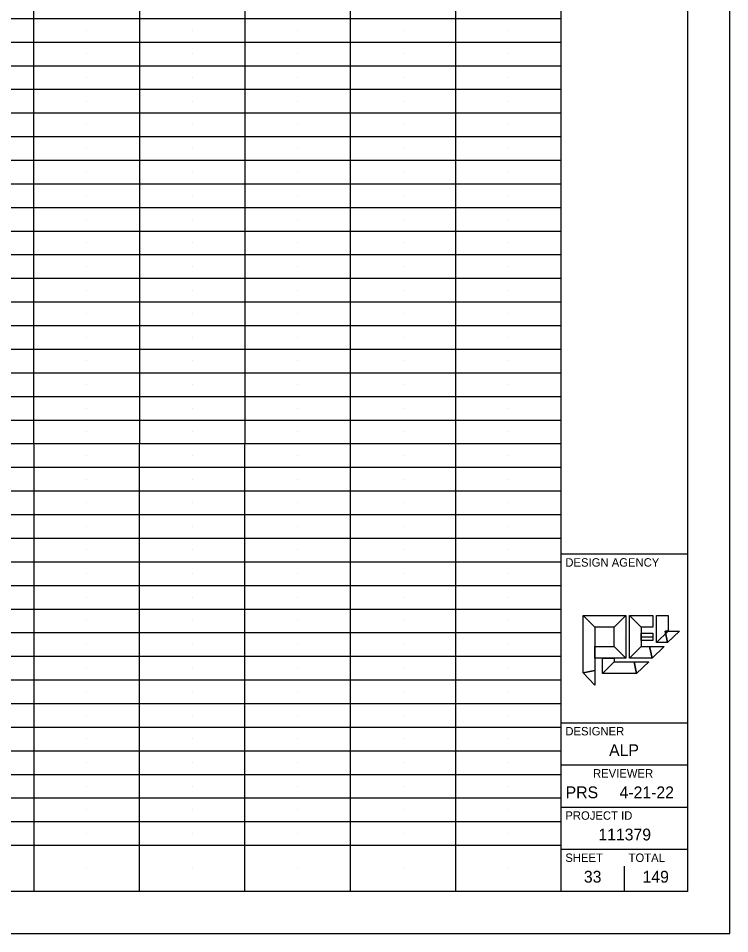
# Model space of a CAD drawing. Extents: x 2073163.9 to 2073197.9, y 634076.5 to 634098.5.
# Drawn here: x 2073189.51 to 2073197.95, y 634076.55 to 634087.4 of the extents above; entities that cross this region are included whole.
import ezdxf

# ---------------------------------------------------------------- set-up
doc = ezdxf.new("R2010")
doc.units = 0
for name, color, linetype in [('Default', 7, 'Continuous'), ('SH_Border', 7, 'Continuous'), ('SH_Cut_Line', 7, 'Continuous'), ('SH_Data', 7, 'Continuous')]:
    doc.layers.add(name, color=color, linetype=linetype)

msp = doc.modelspace()

# ---------------------------------------------------------------- linework, layer by layer
at = {"layer": 'Default'}
msp.add_line((2073196.896, 634080.068), (2073197.032, 634080.068), dxfattribs=at)
for points in [[(2073196.209, 634079.643), (2073196.209, 634080.32), (2073196.347, 634080.183), (2073196.347, 634079.671)], [(2073196.209, 634080.32), (2073196.712, 634080.32), (2073196.576, 634080.183), (2073196.347, 634080.183)], [(2073196.712, 634080.32), (2073196.712, 634079.817), (2073196.576, 634079.954), (2073196.576, 634080.183)], [(2073196.758, 634079.817), (2073196.758, 634080.32), (2073196.896, 634080.183), (2073196.896, 634079.954)], [(2073196.758, 634080.32), (2073197.032, 634080.32), (2073197.032, 634080.183), (2073196.896, 634080.183)], [(2073197.078, 634080), (2073197.078, 634080.32), (2073197.216, 634080.32), (2073197.216, 634080.137)], [(2073197.032, 634080.11), (2073197.032, 634080.026), (2073196.897, 634080.026), (2073196.897, 634080.11)], [(2073197.207, 634080), (2073197.078, 634080), (2073197.216, 634080.137), (2073197.179, 634080.137)], [(2073197.352, 634080.137), (2073197.207, 634080), (2073197.179, 634080.137)], [(2073196.712, 634079.817), (2073196.347, 634079.817), (2073196.347, 634079.954), (2073196.576, 634079.954)], [(2073197.024, 634079.817), (2073196.758, 634079.817), (2073196.896, 634079.954), (2073196.996, 634079.954)], [(2073197.169, 634079.954), (2073197.024, 634079.817), (2073196.996, 634079.954)], [(2073196.438, 634079.634), (2073196.438, 634079.817), (2073196.576, 634079.817), (2073196.576, 634079.771)], [(2073196.841, 634079.634), (2073196.438, 634079.634), (2073196.576, 634079.771), (2073196.812, 634079.771)], [(2073196.987, 634079.771), (2073196.841, 634079.634), (2073196.812, 634079.771)], [(2073196.347, 634079.497), (2073196.209, 634079.643), (2073196.347, 634079.671)]]:
    msp.add_lwpolyline(points, close=True, dxfattribs=at)
at = {"layer": 'SH_Border'}
for p, q in [((2073195.946, 634077.05), (2073195.946, 634098.05)), ((2073195.946, 634081.05), (2073197.446, 634081.05)), ((2073195.946, 634079.05), (2073197.446, 634079.05)), ((2073195.946, 634078.55), (2073197.446, 634078.55)), ((2073195.946, 634078.05), (2073197.446, 634078.05)), ((2073195.946, 634077.55), (2073197.446, 634077.55))]:
    msp.add_line(p, q, dxfattribs=at)
msp.add_lwpolyline([(2073165.446, 634098.05), (2073197.446, 634098.05), (2073197.446, 634077.05), (2073165.446, 634077.05)], close=True, dxfattribs=at)
at = {"layer": 'SH_Cut_Line'}
msp.add_lwpolyline([(2073163.946, 634076.55), (2073197.946, 634076.55), (2073197.946, 634098.55), (2073163.946, 634098.55)], close=True, dxfattribs=at)
at = {"layer": 'SH_Data'}
for p, q in [((2073189.696, 634077.05), (2073189.69, 634098.048)), ((2073190.946, 634077.05), (2073190.95, 634098.05)), ((2073192.196, 634077.05), (2073192.2, 634098.05)), ((2073193.446, 634077.05), (2073193.45, 634098.05)), ((2073194.696, 634077.047), (2073194.7, 634098.047)), ((2073165.446, 634087.398), (2073195.946, 634087.398)), ((2073190.321, 634087.258), (2073190.321, 634087.258)), ((2073191.571, 634087.258), (2073191.571, 634087.258)), ((2073192.821, 634087.258), (2073192.821, 634087.258)), ((2073194.071, 634087.258), (2073194.071, 634087.258)), ((2073195.321, 634087.258), (2073195.321, 634087.258)), ((2073165.446, 634087.118), (2073195.946, 634087.118)), ((2073190.321, 634086.978), (2073190.321, 634086.978)), ((2073191.571, 634086.978), (2073191.571, 634086.978)), ((2073192.821, 634086.978), (2073192.821, 634086.978)), ((2073194.071, 634086.978), (2073194.071, 634086.978)), ((2073195.321, 634086.978), (2073195.321, 634086.978)), ((2073165.446, 634086.838), (2073195.946, 634086.838)), ((2073190.321, 634086.698), (2073190.321, 634086.698)), ((2073191.571, 634086.698), (2073191.571, 634086.698)), ((2073192.821, 634086.698), (2073192.821, 634086.698)), ((2073194.071, 634086.698), (2073194.071, 634086.698)), ((2073195.321, 634086.698), (2073195.321, 634086.698)), ((2073165.446, 634086.558), (2073195.946, 634086.558)), ((2073190.321, 634086.418), (2073190.321, 634086.418)), ((2073191.571, 634086.418), (2073191.571, 634086.418)), ((2073192.821, 634086.418), (2073192.821, 634086.418)), ((2073194.071, 634086.418), (2073194.071, 634086.418)), ((2073195.321, 634086.418), (2073195.321, 634086.418)), ((2073165.446, 634086.278), (2073195.946, 634086.278)), ((2073190.321, 634086.138), (2073190.321, 634086.138)), ((2073191.571, 634086.138), (2073191.571, 634086.138)), ((2073192.821, 634086.138), (2073192.821, 634086.138)), ((2073194.071, 634086.138), (2073194.071, 634086.138)), ((2073195.321, 634086.138), (2073195.321, 634086.138)), ((2073165.446, 634085.998), (2073195.946, 634085.998)), ((2073190.321, 634085.858), (2073190.321, 634085.858)), ((2073191.571, 634085.858), (2073191.571, 634085.858)), ((2073192.821, 634085.858), (2073192.821, 634085.858)), ((2073194.071, 634085.858), (2073194.071, 634085.858)), ((2073195.321, 634085.858), (2073195.321, 634085.858)), ((2073165.446, 634085.718), (2073195.946, 634085.718)), ((2073190.321, 634085.578), (2073190.321, 634085.578)), ((2073191.571, 634085.578), (2073191.571, 634085.578)), ((2073192.821, 634085.578), (2073192.821, 634085.578)), ((2073194.071, 634085.578), (2073194.071, 634085.578)), ((2073195.321, 634085.578), (2073195.321, 634085.578)), ((2073165.446, 634085.438), (2073195.946, 634085.438)), ((2073190.321, 634085.298), (2073190.321, 634085.298)), ((2073191.571, 634085.298), (2073191.571, 634085.298)), ((2073192.821, 634085.298), (2073192.821, 634085.298)), ((2073194.071, 634085.298), (2073194.071, 634085.298)), ((2073195.321, 634085.298), (2073195.321, 634085.298)), ((2073165.446, 634085.158), (2073195.946, 634085.158)), ((2073190.321, 634085.018), (2073190.321, 634085.018)), ((2073191.571, 634085.018), (2073191.571, 634085.018)), ((2073192.821, 634085.018), (2073192.821, 634085.018)), ((2073194.071, 634085.018), (2073194.071, 634085.018)), ((2073195.321, 634085.018), (2073195.321, 634085.018)), ((2073165.446, 634084.878), (2073195.946, 634084.878)), ((2073190.321, 634084.738), (2073190.321, 634084.738)), ((2073191.571, 634084.738), (2073191.571, 634084.738)), ((2073192.821, 634084.738), (2073192.821, 634084.738)), ((2073194.071, 634084.738), (2073194.071, 634084.738)), ((2073195.321, 634084.738), (2073195.321, 634084.738)), ((2073165.446, 634084.598), (2073195.946, 634084.598)), ((2073190.321, 634084.458), (2073190.321, 634084.458)), ((2073191.571, 634084.458), (2073191.571, 634084.458)), ((2073192.821, 634084.458), (2073192.821, 634084.458)), ((2073194.071, 634084.458), (2073194.071, 634084.458)), ((2073195.321, 634084.458), (2073195.321, 634084.458)), ((2073165.446, 634084.318), (2073195.946, 634084.318)), ((2073190.321, 634084.178), (2073190.321, 634084.178)), ((2073191.571, 634084.178), (2073191.571, 634084.178)), ((2073192.821, 634084.178), (2073192.821, 634084.178)), ((2073194.071, 634084.178), (2073194.071, 634084.178)), ((2073195.321, 634084.178), (2073195.321, 634084.178)), ((2073165.446, 634084.038), (2073195.946, 634084.038)), ((2073190.321, 634083.898), (2073190.321, 634083.898)), ((2073191.571, 634083.898), (2073191.571, 634083.898)), ((2073192.821, 634083.898), (2073192.821, 634083.898)), ((2073194.071, 634083.898), (2073194.071, 634083.898)), ((2073195.321, 634083.898), (2073195.321, 634083.898)), ((2073165.446, 634083.758), (2073195.946, 634083.758)), ((2073190.321, 634083.618), (2073190.321, 634083.618)), ((2073191.571, 634083.618), (2073191.571, 634083.618)), ((2073192.821, 634083.618), (2073192.821, 634083.618)), ((2073194.071, 634083.618), (2073194.071, 634083.618)), ((2073195.321, 634083.618), (2073195.321, 634083.618)), ((2073165.446, 634083.478), (2073195.946, 634083.478)), ((2073190.321, 634083.338), (2073190.321, 634083.338)), ((2073191.571, 634083.338), (2073191.571, 634083.338)), ((2073192.821, 634083.338), (2073192.821, 634083.338)), ((2073194.071, 634083.338), (2073194.071, 634083.338)), ((2073195.321, 634083.338), (2073195.321, 634083.338)), ((2073165.446, 634083.198), (2073195.946, 634083.198)), ((2073190.321, 634083.058), (2073190.321, 634083.058)), ((2073191.571, 634083.058), (2073191.571, 634083.058)), ((2073192.821, 634083.058), (2073192.821, 634083.058)), ((2073194.071, 634083.058), (2073194.071, 634083.058)), ((2073195.321, 634083.058), (2073195.321, 634083.058)), ((2073165.446, 634082.918), (2073195.946, 634082.918)), ((2073190.321, 634082.778), (2073190.321, 634082.778)), ((2073191.571, 634082.778), (2073191.571, 634082.778)), ((2073192.821, 634082.778), (2073192.821, 634082.778)), ((2073194.071, 634082.778), (2073194.071, 634082.778)), ((2073195.321, 634082.778), (2073195.321, 634082.778)), ((2073165.446, 634082.638), (2073195.946, 634082.638)), ((2073190.321, 634082.498), (2073190.321, 634082.498)), ((2073191.571, 634082.498), (2073191.571, 634082.498)), ((2073192.821, 634082.498), (2073192.821, 634082.498)), ((2073194.071, 634082.498), (2073194.071, 634082.498)), ((2073195.321, 634082.498), (2073195.321, 634082.498)), ((2073165.446, 634082.358), (2073195.946, 634082.358)), ((2073190.321, 634082.218), (2073190.321, 634082.218)), ((2073191.571, 634082.218), (2073191.571, 634082.218)), ((2073192.821, 634082.218), (2073192.821, 634082.218)), ((2073194.071, 634082.218), (2073194.071, 634082.218)), ((2073195.321, 634082.218), (2073195.321, 634082.218)), ((2073165.446, 634082.078), (2073195.946, 634082.078)), ((2073190.321, 634081.938), (2073190.321, 634081.938)), ((2073191.571, 634081.938), (2073191.571, 634081.938)), ((2073192.821, 634081.938), (2073192.821, 634081.938)), ((2073194.071, 634081.938), (2073194.071, 634081.938)), ((2073195.321, 634081.938), (2073195.321, 634081.938)), ((2073165.446, 634081.798), (2073195.946, 634081.798)), ((2073190.321, 634081.658), (2073190.321, 634081.658)), ((2073191.571, 634081.658), (2073191.571, 634081.658)), ((2073192.821, 634081.658), (2073192.821, 634081.658)), ((2073194.071, 634081.658), (2073194.071, 634081.658)), ((2073195.321, 634081.658), (2073195.321, 634081.658)), ((2073165.446, 634081.518), (2073195.946, 634081.518)), ((2073190.321, 634081.378), (2073190.321, 634081.378)), ((2073191.571, 634081.378), (2073191.571, 634081.378)), ((2073192.821, 634081.378), (2073192.821, 634081.378)), ((2073194.071, 634081.378), (2073194.071, 634081.378)), ((2073195.321, 634081.378), (2073195.321, 634081.378)), ((2073165.446, 634081.238), (2073195.946, 634081.238)), ((2073190.321, 634081.098), (2073190.321, 634081.098)), ((2073191.571, 634081.098), (2073191.571, 634081.098)), ((2073192.821, 634081.098), (2073192.821, 634081.098)), ((2073194.071, 634081.098), (2073194.071, 634081.098)), ((2073195.321, 634081.098), (2073195.321, 634081.098)), ((2073165.446, 634080.958), (2073195.946, 634080.958)), ((2073190.321, 634080.818), (2073190.321, 634080.818)), ((2073191.571, 634080.818), (2073191.571, 634080.818)), ((2073192.821, 634080.818), (2073192.821, 634080.818)), ((2073194.071, 634080.818), (2073194.071, 634080.818)), ((2073195.321, 634080.818), (2073195.321, 634080.818)), ((2073165.446, 634080.678), (2073195.946, 634080.678)), ((2073190.321, 634080.538), (2073190.321, 634080.538)), ((2073191.571, 634080.538), (2073191.571, 634080.538)), ((2073192.821, 634080.538), (2073192.821, 634080.538)), ((2073194.071, 634080.538), (2073194.071, 634080.538)), ((2073195.321, 634080.538), (2073195.321, 634080.538)), ((2073165.446, 634080.398), (2073195.946, 634080.398)), ((2073190.321, 634080.258), (2073190.321, 634080.258)), ((2073191.571, 634080.258), (2073191.571, 634080.258)), ((2073192.821, 634080.258), (2073192.821, 634080.258)), ((2073194.071, 634080.258), (2073194.071, 634080.258)), ((2073195.321, 634080.258), (2073195.321, 634080.258)), ((2073165.446, 634080.118), (2073195.946, 634080.118)), ((2073196.696, 634080.05), (2073196.696, 634080.05)), ((2073190.321, 634079.978), (2073190.321, 634079.978)), ((2073191.571, 634079.978), (2073191.571, 634079.978)), ((2073192.821, 634079.978), (2073192.821, 634079.978)), ((2073194.071, 634079.978), (2073194.071, 634079.978)), ((2073195.321, 634079.978), (2073195.321, 634079.978)), ((2073165.446, 634079.838), (2073195.946, 634079.838)), ((2073190.321, 634079.698), (2073190.321, 634079.698)), ((2073191.571, 634079.698), (2073191.571, 634079.698)), ((2073192.821, 634079.698), (2073192.821, 634079.698)), ((2073194.071, 634079.698), (2073194.071, 634079.698)), ((2073195.321, 634079.698), (2073195.321, 634079.698)), ((2073165.446, 634079.558), (2073195.946, 634079.558)), ((2073190.321, 634079.418), (2073190.321, 634079.418)), ((2073191.571, 634079.418), (2073191.571, 634079.418)), ((2073192.821, 634079.418), (2073192.821, 634079.418)), ((2073194.071, 634079.418), (2073194.071, 634079.418)), ((2073195.321, 634079.418), (2073195.321, 634079.418)), ((2073165.446, 634079.278), (2073195.946, 634079.278)), ((2073190.321, 634079.138), (2073190.321, 634079.138)), ((2073191.571, 634079.138), (2073191.571, 634079.138)), ((2073192.821, 634079.138), (2073192.821, 634079.138)), ((2073194.071, 634079.138), (2073194.071, 634079.138)), ((2073195.321, 634079.138), (2073195.321, 634079.138)), ((2073165.446, 634078.998), (2073195.946, 634078.998)), ((2073190.321, 634078.858), (2073190.321, 634078.858)), ((2073191.571, 634078.858), (2073191.571, 634078.858)), ((2073192.821, 634078.858), (2073192.821, 634078.858)), ((2073194.071, 634078.858), (2073194.071, 634078.858)), ((2073195.321, 634078.858), (2073195.321, 634078.858)), ((2073165.446, 634078.718), (2073195.946, 634078.718)), ((2073190.321, 634078.578), (2073190.321, 634078.578)), ((2073191.571, 634078.578), (2073191.571, 634078.578)), ((2073192.821, 634078.578), (2073192.821, 634078.578)), ((2073194.071, 634078.578), (2073194.071, 634078.578)), ((2073195.321, 634078.578), (2073195.321, 634078.578)), ((2073165.446, 634078.438), (2073195.946, 634078.438)), ((2073190.321, 634078.298), (2073190.321, 634078.298)), ((2073191.571, 634078.298), (2073191.571, 634078.298)), ((2073192.821, 634078.298), (2073192.821, 634078.298)), ((2073194.071, 634078.298), (2073194.071, 634078.298)), ((2073195.321, 634078.298), (2073195.321, 634078.298)), ((2073165.446, 634078.158), (2073195.946, 634078.158)), ((2073190.321, 634078.018), (2073190.321, 634078.018)), ((2073191.571, 634078.018), (2073191.571, 634078.018)), ((2073192.821, 634078.018), (2073192.821, 634078.018)), ((2073194.071, 634078.018), (2073194.071, 634078.018)), ((2073195.321, 634078.018), (2073195.321, 634078.018)), ((2073165.446, 634077.878), (2073195.946, 634077.878)), ((2073190.321, 634077.738), (2073190.321, 634077.738)), ((2073191.571, 634077.738), (2073191.571, 634077.738)), ((2073192.821, 634077.738), (2073192.821, 634077.738)), ((2073194.071, 634077.738), (2073194.071, 634077.738)), ((2073195.321, 634077.738), (2073195.321, 634077.738)), ((2073165.446, 634077.598), (2073195.946, 634077.598)), ((2073190.321, 634077.324), (2073190.321, 634077.324)), ((2073191.571, 634077.324), (2073191.571, 634077.324)), ((2073192.821, 634077.324), (2073192.821, 634077.324)), ((2073194.071, 634077.324), (2073194.071, 634077.324)), ((2073195.321, 634077.324), (2073195.321, 634077.324)), ((2073196.696, 634077.05), (2073196.696, 634077.35)), ((2073196.321, 634077.225), (2073196.321, 634077.225))]:
    msp.add_line(p, q, dxfattribs=at)

# ---------------------------------------------------------------- texts
for s, height, p in [('DESIGN AGENCY', 0.1, (2073195.996, 634080.9)), ('DESIGNER', 0.1, (2073195.996, 634078.9)), ('ALP', 0.14, (2073196.515, 634078.655)), ('REVIEWER', 0.1, (2073196.324, 634078.4)), ('PRS', 0.14, (2073196, 634078.155)), ('4-21-22', 0.14, (2073196.639, 634078.155)), ('PROJECT ID', 0.1, (2073195.996, 634077.9)), ('111379', 0.14, (2073196.388, 634077.655)), ('SHEET', 0.1, (2073195.996, 634077.4)), ('TOTAL', 0.1, (2073196.746, 634077.4)), ('33', 0.14, (2073196.216, 634077.155)), ('149', 0.14, (2073196.912, 634077.155))]:
    msp.add_text(s, height=height, dxfattribs=at).set_placement(p)

doc.saveas('drawing.dxf')
